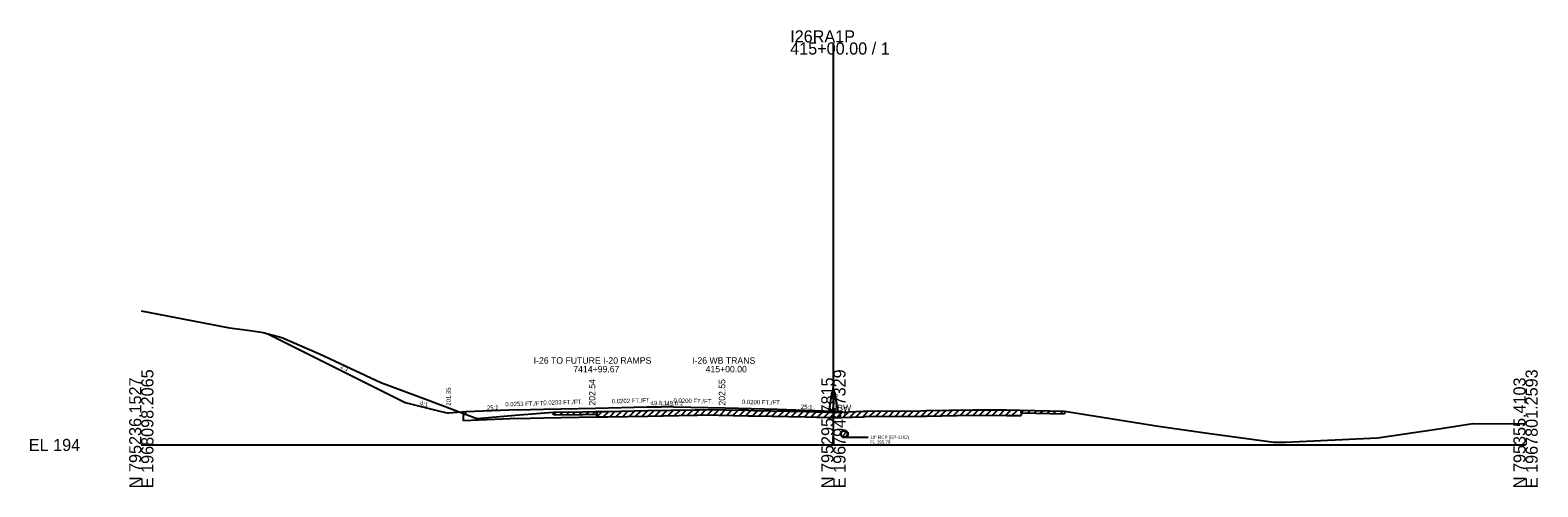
# Model space of a CAD drawing. Extents: x -44 to 4323, y -10 to 9601.
# Drawn here: x -25.7 to 322.8, y 8990.3 to 9095.9 of the extents above; entities that cross this region are included whole.
import ezdxf

# ---------------------------------------------------------------- set-up
doc = ezdxf.new("R2010")
doc.units = 0
for name, color, linetype in [('1', 7, 'Continuous'), ('DateStamp', 7, 'Continuous'), ('NotForConst', 7, 'Continuous'), ('QCQA', 7, 'Continuous'), ('RD_SHT_Bndy', 7, 'Continuous'), ('RD_SHT_Iplotshp', 7, 'Continuous'), ('RD_SHT_TX', 7, 'Continuous'), ('RD_TX_Misc1', 7, 'Continuous'), ('RD_XS_ExGround', 7, 'Continuous'), ('RD_XS_Misc_Line', 7, 'Continuous'), ('RD_XS_Pave', 7, 'Continuous'), ('RD_XS_PaveShd', 7, 'Continuous'), ('RD_XS_Pipe', 7, 'Continuous'), ('RD_XS_TX_Elev_PR', 7, 'Continuous'), ('RD_XS_TX_Profile', 7, 'Continuous'), ('RD_XS_TX_ShdSlope', 7, 'Continuous'), ('RD_XS_TX_Slope', 7, 'Continuous'), ('seal', 7, 'Continuous'), ('TR SN EXTRUDED PANEL SIGNS - GROUND MOUNTED', 7, 'Continuous')]:
    doc.layers.add(name, color=color, linetype=linetype)

msp = doc.modelspace()

# ---------------------------------------------------------------- linework, layer by layer
at = {"layer": 'DateStamp'}
msp.add_lwpolyline([(0, 9031.03), (20.41, 9027.07), (25.17, 9026.47), (28.17, 9026), (32.48, 9024.88), (41.17, 9021.09), (55.4, 9014.44), (66.13, 9010.44), (77.55, 9006.13), (87.39, 9006.94), (95.28, 9007.59), (102.08, 9007.67), (105.01, 9007.71), (107.79, 9007.77), (117.04, 9007.94), (127.88, 9008.14), (128.57, 9008.15), (130.06, 9008.18), (140.2, 9008.02), (141.61, 9008), (145.74, 9007.91), (153.57, 9007.74), (158.79, 9007.58), (159.11, 9007.57), (160, 9007.58), (161.79, 9007.62), (166.85, 9007.78), (167.39, 9007.8), (180.18, 9007.92), (181.55, 9007.94), (192.13, 9008.16), (200.01, 9008.09), (203.13, 9008.06), (213.39, 9007.82), (235.15, 9004.38), (246.49, 9002.73), (261.79, 9000.66), (264.43, 9000.67), (271.04, 9000.96), (285.75, 9001.63), (299.98, 9003.73), (307.79, 9004.93), (320, 9004.89)], dxfattribs=at)
at = {"layer": 'NotForConst'}
for p, q in [((95.28, 9006.96), (95.91, 9007.6)), ((96.78, 9006.98), (97.41, 9007.61)), ((98.28, 9007), (98.91, 9007.63)), ((99.78, 9007.02), (100.41, 9007.65)), ((101.28, 9007.04), (101.91, 9007.67)), ((102.78, 9007.06), (103.42, 9007.69)), ((104.28, 9007.08), (104.92, 9007.71)), ((105.28, 9006.47), (106.56, 9007.74)), ((106.78, 9006.5), (108.06, 9007.77)), ((108.28, 9006.53), (109.56, 9007.8)), ((109.78, 9006.56), (111.06, 9007.83)), ((111.28, 9006.58), (112.56, 9007.86)), ((112.78, 9006.61), (114.06, 9007.89)), ((114.28, 9006.64), (115.56, 9007.91)), ((115.78, 9006.67), (117.06, 9007.94)), ((117.28, 9006.7), (118.56, 9007.97)), ((118.78, 9006.72), (120.06, 9008)), ((120.28, 9006.75), (121.56, 9008.02)), ((121.78, 9006.78), (123.06, 9008.05)), ((123.28, 9006.81), (124.56, 9008.08)), ((124.78, 9006.83), (126.06, 9008.11)), ((126.28, 9006.86), (127.56, 9008.13)), ((127.78, 9006.89), (129.05, 9008.16)), ((129.28, 9006.91), (130.54, 9008.17)), ((130.78, 9006.92), (132.01, 9008.15)), ((132.28, 9006.89), (133.51, 9008.12)), ((133.78, 9006.87), (135.01, 9008.1)), ((135.28, 9006.85), (136.51, 9008.08)), ((136.78, 9006.82), (138.01, 9008.06)), ((138.28, 9006.8), (139.51, 9008.03)), ((139.78, 9006.78), (141.01, 9008.01)), ((141.28, 9006.76), (142.51, 9007.98)), ((142.78, 9006.73), (144, 9007.95)), ((144.28, 9006.69), (145.5, 9007.92)), ((145.78, 9006.66), (147.01, 9007.88)), ((147.28, 9006.63), (148.51, 9007.85)), ((148.78, 9006.6), (150.01, 9007.82)), ((150.28, 9006.56), (151.51, 9007.79)), ((151.78, 9006.53), (153.01, 9007.75)), ((153.28, 9006.5), (154.5, 9007.71)), ((154.78, 9006.45), (155.99, 9007.66)), ((156.28, 9006.41), (157.49, 9007.62)), ((157.78, 9006.36), (159, 9007.57)), ((159.28, 9006.32), (160.55, 9007.6)), ((160.78, 9006.35), (162.06, 9007.63)), ((162.28, 9006.39), (163.57, 9007.68)), ((163.78, 9006.43), (165.07, 9007.73)), ((165.28, 9006.48), (166.57, 9007.78)), ((166.78, 9006.53), (168.06, 9007.81)), ((168.28, 9006.56), (169.54, 9007.82)), ((169.78, 9006.57), (171.04, 9007.83)), ((171.28, 9006.59), (172.54, 9007.85)), ((172.78, 9006.6), (174.04, 9007.86)), ((174.28, 9006.61), (175.54, 9007.87)), ((175.78, 9006.63), (177.04, 9007.89)), ((177.28, 9006.64), (178.54, 9007.9)), ((178.78, 9006.65), (180.04, 9007.91)), ((180.28, 9006.67), (181.56, 9007.94)), ((181.78, 9006.7), (183.06, 9007.97)), ((183.28, 9006.73), (184.56, 9008)), ((184.78, 9006.76), (186.06, 9008.04)), ((186.28, 9006.79), (187.56, 9008.07)), ((187.78, 9006.82), (189.06, 9008.1)), ((189.28, 9006.85), (190.56, 9008.13)), ((190.78, 9006.88), (192.06, 9008.16)), ((192.28, 9006.91), (193.52, 9008.15)), ((193.78, 9006.89), (195.02, 9008.13)), ((195.28, 9006.88), (196.52, 9008.12)), ((196.78, 9006.87), (198.02, 9008.11)), ((198.28, 9006.85), (199.52, 9008.09)), ((199.78, 9006.84), (201.02, 9008.08)), ((201.28, 9006.83), (202.52, 9008.07)), ((203.39, 9007.43), (204, 9008.04)), ((204.89, 9007.39), (205.5, 9008)), ((206.39, 9007.36), (207, 9007.97)), ((207.89, 9007.32), (208.5, 9007.93)), ((209.39, 9007.29), (210, 9007.9)), ((210.89, 9007.25), (211.5, 9007.86)), ((212.39, 9007.22), (213, 9007.83))]:
    msp.add_line(p, q, dxfattribs=at)
at = {"layer": 'QCQA'}
for p, q in [((105.28, 9007.72), (107.79, 9007.77)), ((105.28, 9007.72), (105.28, 9006.51)), ((107.79, 9007.77), (117.04, 9007.94)), ((117.04, 9007.94), (127.88, 9008.14)), ((127.88, 9008.14), (128.57, 9008.15)), ((128.57, 9008.15), (130.06, 9008.18)), ((130.06, 9008.18), (140.2, 9008.02)), ((140.2, 9008.02), (141.61, 9008)), ((141.61, 9008), (145.74, 9007.91)), ((145.74, 9007.91), (153.57, 9007.74)), ((153.57, 9007.74), (158.79, 9007.58)), ((158.79, 9007.58), (159.11, 9007.57)), ((159.11, 9007.57), (160, 9007.58))]:
    msp.add_line(p, q, dxfattribs=at)
at = {"layer": 'RD_SHT_Bndy'}
for p, q in [((160, 9000), (160, 9093.1)), ((0, 9000), (160, 9000)), ((160, 9000), (320, 9000))]:
    msp.add_line(p, q, dxfattribs=at)
at = {"layer": 'RD_SHT_Iplotshp'}
for p, q in [((95.28, 9006.96), (95.28, 9007.59)), ((95.28, 9006.96), (102.08, 9007.05)), ((102.08, 9007.05), (105.01, 9007.09)), ((105.01, 9007.09), (105.28, 9007.1)), ((105.28, 9006.47), (105.28, 9007.72)), ((105.28, 9007.72), (105.28, 9007.1)), ((105.28, 9006.47), (107.79, 9006.52)), ((107.79, 9006.52), (117.04, 9006.69)), ((117.04, 9006.69), (127.88, 9006.89)), ((127.88, 9006.89), (128.57, 9006.9)), ((128.57, 9006.9), (130.06, 9006.93)), ((130.06, 9006.93), (140.2, 9006.77)), ((140.2, 9006.77), (141.61, 9006.75)), ((141.61, 9006.75), (145.74, 9006.66)), ((145.74, 9006.66), (153.57, 9006.49)), ((153.57, 9006.49), (158.79, 9006.33)), ((158.79, 9006.33), (159.11, 9006.32)), ((159.11, 9006.32), (160, 9006.33)), ((160, 9006.33), (161.79, 9006.37)), ((161.79, 9006.37), (166.85, 9006.53)), ((166.85, 9006.53), (167.39, 9006.55)), ((167.39, 9006.55), (180.18, 9006.67)), ((180.18, 9006.67), (181.55, 9006.69)), ((181.55, 9006.69), (192.13, 9006.91)), ((192.13, 9006.91), (200.01, 9006.84)), ((200.01, 9006.84), (203.13, 9006.81)), ((203.13, 9006.81), (203.39, 9006.8)), ((203.39, 9008.05), (203.39, 9006.8)), ((203.39, 9007.43), (203.39, 9008.05)), ((203.39, 9007.43), (213.39, 9007.19)), ((213.39, 9007.82), (213.39, 9007.19))]:
    msp.add_line(p, q, dxfattribs=at)
at = {"layer": 'RD_TX_Misc1'}
for p in [(69, 9007.85), (73, 9007.51)]:
    msp.add_line(p, (71, 9007.35), dxfattribs=at)
at = {"layer": 'RD_XS_Misc_Line'}
for p, q in [((74.5, 9007.09), (75, 9007.11)), ((74.5, 9005.61), (74.5, 9007.09)), ((87, 9006.11), (74.5, 9005.61)), ((75, 9007.11), (75, 9007.67)), ((87, 9006.11), (92.97, 9006.26)), ((92.97, 9006.26), (105.28, 9006.51))]:
    msp.add_line(p, q, dxfattribs=at)
at = {"layer": 'RD_XS_Pave'}
for p, q in [((29.25, 9025.72), (61, 9009.85)), ((61, 9009.85), (69, 9007.85))]:
    msp.add_line(p, q, dxfattribs=at)
at = {"layer": 'RD_XS_PaveShd'}
msp.add_line((75, 9007.67), (73, 9007.51), dxfattribs=at)
at = {"layer": 'RD_XS_Pipe'}
msp.add_line((163.01, 9001.79), (168.01, 9001.79), dxfattribs=at)
for radius in [0.85, 0.75]:
    msp.add_circle((162.51, 9002.54), radius, dxfattribs=at)
at = {"layer": 'RD_XS_TX_Elev_PR'}
for p, q in [((87, 9008.15), (75, 9007.67)), ((116.98, 9008.78), (120.24, 9008.85)), ((123, 9008.79), (120.24, 9008.85)), ((147, 9008.31), (160, 9007.79)), ((160, 9007.78), (160, 9007.58))]:
    msp.add_line(p, q, dxfattribs=at)
at = {"layer": 'RD_XS_TX_ShdSlope'}
for p, q in [((159, 9007.81), (159.67, 9012.29)), ((160.33, 9012.29), (159.67, 9012.29)), ((161, 9007.8), (160.33, 9012.29))]:
    msp.add_line(p, q, dxfattribs=at)
at = {"layer": 'RD_XS_TX_Slope'}
for p, q in [((87, 9008.15), (92.97, 9008.3)), ((92.97, 9008.3), (104.98, 9008.54)), ((104.98, 9008.54), (116.98, 9008.78)), ((123, 9008.79), (135, 9008.55)), ((135, 9008.55), (147, 9008.31))]:
    msp.add_line(p, q, dxfattribs=at)

# ---------------------------------------------------------------- texts
at = {"layer": '1'}
for s, p in [('I-26 TO FUTURE I-20 RAMPS', (90.7, 9018.79)), ('I-26 WB TRANS', (127.33, 9018.79)), ('7414+99.67', (99.87, 9016.79)), ('415+00.00', (130.45, 9016.79))]:
    msp.add_text(s, height=1.5, dxfattribs=at).set_placement(p)
at = {"layer": 'RD_SHT_Bndy'}
for s, p in [('415+00.00 / 1', (150, 9090.3)), ('I26RA1P', (150, 9093.1)), ('EL 194', (-26, 8998.6))]:
    msp.add_text(s, height=2.8, dxfattribs=at).set_placement(p)
for s, p in [('E 1968098.2065', (2.8, 8990)), ('E 1967949.7329', (162.8, 8990)), ('E 1967801.2593', (322.8, 8990)), ('N 795236.1527', (0, 8990)), ('N 795295.7815', (160, 8990)), ('N 795355.4103', (320, 8990))]:
    msp.add_text(s, height=2.8, rotation=90, dxfattribs=at).set_placement(p)
at = {"layer": 'RD_SHT_TX'}
msp.add_text('201.58', height=1, rotation=90, dxfattribs=at).set_placement((161, 9007.58))
at = {"layer": 'RD_XS_ExGround'}
for s, rotation, p in [('49.6:1', 1.1561, (117.74, 9009.17)), ('49.6:1', 1.1561, (121.4, 9009.12)), ('25:1', 2.29, (79.93, 9008.11)), ('25:1', 357.7094, (152.46, 9008.34))]:
    msp.add_text(s, height=1, rotation=rotation, dxfattribs=at).set_placement(p)
at = {"layer": 'RD_XS_Pipe'}
for s, p in [('18" RCP (EP-1162)', (168.51, 9001.41)), ('FL 195.79', (168.51, 9000.29))]:
    msp.add_text(s, height=0.75, dxfattribs=at).set_placement(p)
at = {"layer": 'RD_XS_TX_Profile'}
msp.add_text('WBW', height=1.5, dxfattribs=at).set_placement((159, 9007.81))
at = {"layer": 'seal'}
for s, p in [(' 202.54', (104.98, 9008.54)), (' 202.55', (135, 9008.54))]:
    msp.add_text(s, height=1.5, rotation=90, dxfattribs=at).set_placement(p)
at = {"layer": 'TR SN EXTRUDED PANEL SIGNS - GROUND MOUNTED'}
for s, rotation, p in [('2:1', 333.4349, (45.97, 9017.82)), ('201.35', 90, (71.5, 9009.08)), ('4:1', 345.9638, (64.31, 9009.25)), ('0.0253 FT./FT.', 1.4477, (84.16, 9008.92)), ('0.0203 FT./FT.', 1.1612, (92.95, 9009.3)), ('0.0202 FT./FT.', 1.1561, (108.77, 9009.62)), ('0.0200 FT./FT.', 358.8542, (123.02, 9009.78)), ('0.0200 FT./FT.', 358.8542, (138.83, 9009.47))]:
    msp.add_text(s, height=1, rotation=rotation, dxfattribs=at).set_placement(p)

doc.saveas('drawing.dxf')
